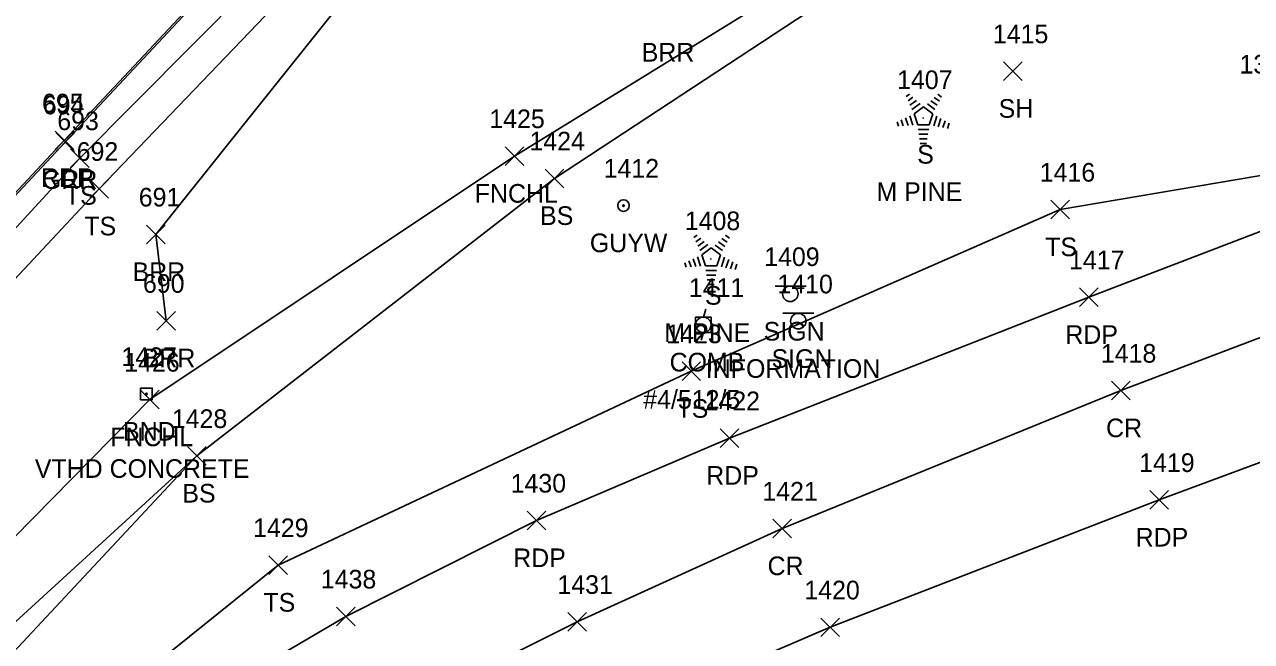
# Model space of a CAD drawing. Extents: x 1688195 to 1692013, y 424605 to 441234.
# Drawn here: x 1691586.4 to 1691718.1, y 439041.4 to 439107.6 of the extents above; entities that cross this region are included whole.
import ezdxf

# ---------------------------------------------------------------- set-up
doc = ezdxf.new("R2010")
doc.units = 0
for name, color, linetype in [('L_A', 7, 'Continuous'), ('L_C', 7, 'Continuous'), ('L_I', 7, 'Continuous'), ('L_TIC', 7, 'Continuous'), ('LABL', 7, 'Continuous'), ('LELB', 7, 'Continuous'), ('Level 18', 7, 'Continuous'), ('LFNC', 7, 'Continuous'), ('LTC', 7, 'Continuous'), ('M_A', 7, 'Continuous'), ('M_C', 7, 'Continuous'), ('M_I', 7, 'Continuous'), ('P_A', 7, 'Continuous'), ('P_I', 7, 'Continuous'), ('P_TIC', 7, 'Continuous'), ('PET', 7, 'Continuous'), ('PRC', 7, 'Continuous'), ('R_A', 7, 'Continuous'), ('R_I', 7, 'Continuous'), ('R_TIC', 7, 'Continuous'), ('RGR', 7, 'Continuous'), ('S_A', 7, 'Continuous'), ('S_C', 7, 'Continuous'), ('S_I', 7, 'Continuous'), ('SSGN', 7, 'Continuous'), ('U_A', 7, 'Continuous'), ('U_C', 7, 'Continuous'), ('U_I', 7, 'Continuous'), ('UP', 7, 'Continuous'), ('UPGW', 7, 'Continuous')]:
    doc.layers.add(name, color=color, linetype=linetype)

msp = doc.modelspace()

# ---------------------------------------------------------------- linework, layer by layer
at = {"layer": 'L_TIC'}
for points in [[(1691691.44, 439101.58), (1691693.44, 439103.58)], [(1691693.44, 439101.58), (1691691.44, 439103.58)], [(1691591.32, 439092.25), (1691593.32, 439094.25)], [(1691593.32, 439092.25), (1691591.32, 439094.25)], [(1691637.96, 439092.47), (1691639.96, 439094.47)], [(1691639.96, 439092.47), (1691637.96, 439094.47)], [(1691642.28, 439090.08), (1691644.28, 439092.08)], [(1691644.28, 439090.08), (1691642.28, 439092.08)], [(1691593.4, 439088.96), (1691595.4, 439090.96)], [(1691595.4, 439088.96), (1691593.4, 439090.96)], [(1691696.52, 439086.73), (1691698.52, 439088.73)], [(1691698.52, 439086.73), (1691696.52, 439088.73)], [(1691599.49, 439084.06), (1691601.49, 439086.06)], [(1691601.49, 439084.06), (1691599.49, 439086.06)], [(1691600.59, 439074.8), (1691602.59, 439076.8)], [(1691602.59, 439074.8), (1691600.59, 439076.8)], [(1691656.95, 439069.39), (1691658.95, 439071.39)], [(1691658.95, 439069.39), (1691656.95, 439071.39)], [(1691598.84, 439066.34), (1691600.84, 439068.34)], [(1691600.84, 439066.34), (1691598.84, 439068.34)], [(1691603.89, 439060.29), (1691605.89, 439062.29)], [(1691605.89, 439060.29), (1691603.89, 439062.29)], [(1691603.89, 439060.29), (1691605.89, 439062.29)], [(1691605.89, 439060.29), (1691603.89, 439062.29)], [(1691612.62, 439048.58), (1691614.62, 439050.58)], [(1691614.62, 439048.58), (1691612.62, 439050.58)]]:
    msp.add_lwpolyline(points, dxfattribs=at)
at = {"layer": 'LABL'}
msp.add_lwpolyline([(1691601.59, 439075.8), (1691600.49, 439085.06), (1691627.74, 439119.17), (1691640.71, 439127.56), (1691655.14, 439108.61), (1691685.11, 439134.92), (1691687.62, 439141.73), (1691698.9, 439155.76), (1691733.43, 439157.4), (1691776.41, 439186.57), (1691794.38, 439190.21)], dxfattribs=at)
at = {"layer": 'LELB'}
for points in [[(1691809.05, 439198.7), (1691810.07, 439220.42), (1691810.47, 439227.71), (1691810.04, 439233.75), (1691820.98, 439231.16), (1691837.25, 439226.41), (1691844.55, 439222.68), (1691860.67, 439213.28), (1691879.41, 439197.19), (1691884.86, 439187.77), (1691888.44, 439178.13), (1691882, 439154.55), (1691849.25, 439142.61), (1691815.33, 439128.47), (1691761.5, 439106.68), (1691722.87, 439092.03), (1691697.52, 439087.73), (1691657.95, 439070.39), (1691613.62, 439049.58), (1691576.98, 439020.14), (1691544.83, 438993.15), (1691508.2, 438954.88), (1691488.69, 438935.2)], [(1691494.97, 438989.23), (1691529.39, 439026.47), (1691563.11, 439061.46), (1691592.32, 439093.25), (1691622.45, 439123.57), (1691640.28, 439144.55), (1691642.63, 439146.18), (1691644.54, 439148.64), (1691657.14, 439160.25), (1691677.5, 439185.53), (1691687.79, 439198.06), (1691700.53, 439206.6), (1691711.71, 439214.4), (1691729.93, 439221), (1691765.22, 439228.65), (1691785.8, 439230.06)], [(1691867.08, 439165.21), (1691844.95, 439160.27), (1691798.84, 439152.11), (1691745.51, 439147.11), (1691728.71, 439142.4), (1691709.09, 439133.88), (1691683, 439117.2), (1691643.28, 439091.08), (1691604.89, 439061.29), (1691572.53, 439026.72), (1691542.38, 438995.55), (1691505.84, 438957.5), (1691487.66, 438936.34), (1691466.81, 438915.54), (1691436.02, 438880.86), (1691415.55, 438858.76)], [(1691497.62, 438986.55), (1691532.48, 439023.13), (1691565.52, 439059.1), (1691594.4, 439089.96), (1691624.94, 439121.84), (1691642.24, 439143.61)], [(1691604.89, 439061.29), (1691570.2, 439029.58), (1691540.68, 438997.55), (1691504.19, 438958.83), (1691485.94, 438937.8), (1691466.29, 438916.24), (1691434.59, 438882.45), (1691414.01, 438860.1)]]:
    msp.add_lwpolyline(points, dxfattribs=at)
at = {"layer": 'Level 18'}
msp.add_lwpolyline([(1691598.85, 439068.57), (1691600.1, 439068.57), (1691600.1, 439067.32), (1691598.85, 439067.32)], close=True, dxfattribs=at)
msp.add_circle((1691599.48, 439067.94), 0.0833, dxfattribs=at)
at = {"layer": 'LFNC'}
msp.add_lwpolyline([(1691844.63, 439219.19), (1691827.3, 439208.18), (1691808.98, 439197.07), (1691805.18, 439194.78), (1691802.65, 439193.15), (1691780.93, 439179.95), (1691740.49, 439155.55), (1691707.63, 439134.9), (1691682.09, 439120.04), (1691638.96, 439093.47), (1691599.84, 439067.34), (1691566.38, 439033.38), (1691536.95, 439001.22), (1691500.89, 438961.26), (1691462.91, 438919.55), (1691429.39, 438883.14), (1691411.26, 438863.12)], dxfattribs=at)
at = {"layer": 'LTC'}
for p, q in [((1691681, 439099.87), (1691681.35, 439100.12)), ((1691681.21, 439099.4), (1691681.73, 439099.79)), ((1691681.41, 439098.94), (1691682.12, 439099.45)), ((1691683.65, 439099.41), (1691684.33, 439098.92)), ((1691684.02, 439099.76), (1691684.57, 439099.36)), ((1691684.39, 439100.11), (1691684.81, 439099.8)), ((1691681.62, 439098.47), (1691682.5, 439099.11)), ((1691681.85, 439098.01), (1691682.86, 439098.75)), ((1691681.85, 439098.01), (1691682.24, 439096.82)), ((1691682.86, 439098.75), (1691683.86, 439098.02)), ((1691683.28, 439099.06), (1691684.09, 439098.47)), ((1691683.86, 439098.02), (1691683.47, 439096.82)), ((1691680.03, 439097.15), (1691680.18, 439096.68)), ((1691680.48, 439097.36), (1691680.7, 439096.71)), ((1691680.94, 439097.58), (1691681.21, 439096.74)), ((1691681.39, 439097.8), (1691681.73, 439096.78)), ((1691683.47, 439096.82), (1691682.24, 439096.82)), ((1691684.3, 439097.75), (1691683.96, 439096.71)), ((1691684.74, 439097.5), (1691684.45, 439096.62)), ((1691685.18, 439097.25), (1691684.95, 439096.52)), ((1691685.63, 439097), (1691685.44, 439096.43)), ((1691683.43, 439096.32), (1691682.28, 439096.32)), ((1691683.34, 439095.82), (1691682.36, 439095.82)), ((1691683.26, 439095.32), (1691682.43, 439095.32)), ((1691683.18, 439094.82), (1691682.5, 439094.82)), ((1691658.22, 439084.73), (1691658.57, 439084.99)), ((1691661.61, 439084.97), (1691662.03, 439084.66)), ((1691658.43, 439084.26), (1691658.96, 439084.65)), ((1691658.64, 439083.8), (1691659.34, 439084.31)), ((1691658.85, 439083.33), (1691659.72, 439083.97)), ((1691659.07, 439082.88), (1691660.08, 439083.61)), ((1691660.08, 439083.61), (1691661.08, 439082.89)), ((1691660.5, 439083.92), (1691661.31, 439083.33)), ((1691660.87, 439084.27), (1691661.55, 439083.78)), ((1691661.24, 439084.62), (1691661.79, 439084.22)), ((1691657.7, 439082.22), (1691657.92, 439081.57)), ((1691658.16, 439082.44), (1691658.43, 439081.61)), ((1691658.62, 439082.66), (1691658.95, 439081.64)), ((1691659.07, 439082.88), (1691659.46, 439081.68)), ((1691661.08, 439082.89), (1691660.69, 439081.68)), ((1691661.52, 439082.61), (1691661.18, 439081.58)), ((1691661.96, 439082.36), (1691661.67, 439081.48)), ((1691662.41, 439082.11), (1691662.17, 439081.38)), ((1691657.25, 439082.01), (1691657.4, 439081.54)), ((1691660.69, 439081.68), (1691659.46, 439081.68)), ((1691660.65, 439081.18), (1691659.5, 439081.18)), ((1691662.85, 439081.86), (1691662.66, 439081.29)), ((1691660.57, 439080.68), (1691659.58, 439080.68)), ((1691660.48, 439080.18), (1691659.65, 439080.18)), ((1691660.4, 439079.68), (1691659.72, 439079.68))]:
    msp.add_line(p, q, dxfattribs=at)
at = {"layer": 'P_TIC'}
for points in [[(1691589.68, 439094.16), (1691591.68, 439096.16)], [(1691591.68, 439094.16), (1691589.68, 439096.16)], [(1691699.6, 439077.32), (1691701.6, 439079.32)], [(1691701.6, 439077.32), (1691699.6, 439079.32)], [(1691703.03, 439067.3), (1691705.03, 439069.3)], [(1691705.03, 439067.3), (1691703.03, 439069.3)], [(1691661.06, 439062.2), (1691663.06, 439064.2)], [(1691663.06, 439062.2), (1691661.06, 439064.2)], [(1691707.14, 439055.57), (1691709.14, 439057.57)], [(1691709.14, 439055.57), (1691707.14, 439057.57)], [(1691640.34, 439053.36), (1691642.34, 439055.36)], [(1691642.34, 439053.36), (1691640.34, 439055.36)], [(1691666.7, 439052.5), (1691668.7, 439054.5)], [(1691668.7, 439052.5), (1691666.7, 439054.5)], [(1691619.88, 439043.07), (1691621.88, 439045.07)], [(1691621.88, 439043.07), (1691619.88, 439045.07)], [(1691644.71, 439042.49), (1691646.71, 439044.49)], [(1691646.71, 439042.49), (1691644.71, 439044.49)], [(1691671.86, 439041.9), (1691673.86, 439043.9)], [(1691673.86, 439041.9), (1691671.86, 439043.9)]]:
    msp.add_lwpolyline(points, dxfattribs=at)
at = {"layer": 'PET'}
for points in [[(1691527.98, 439028.02), (1691561.01, 439063.43), (1691590.68, 439095.16), (1691619.98, 439126.48), (1691638.57, 439146.32), (1691653.83, 439162.94), (1691673.33, 439185.49), (1691673.65, 439189.01), (1691685.04, 439200.74), (1691697.53, 439210.68), (1691709.71, 439218.34), (1691715.71, 439221.67), (1691737.08, 439230.06)], [(1691962.88, 439130.56), (1691955.64, 439134.26), (1691948.02, 439136.72), (1691941.11, 439138.03), (1691934.22, 439138.24), (1691927.22, 439137.24), (1691921.33, 439135.77), (1691915.1, 439134.27), (1691873.49, 439117.66), (1691865.77, 439114.89), (1691827.16, 439101.41), (1691792.77, 439088.6), (1691761.14, 439076.62), (1691734.19, 439066.23), (1691708.14, 439056.57), (1691672.86, 439042.9), (1691649.54, 439032.89)], [(1691724.96, 439087.65), (1691700.6, 439078.32), (1691662.06, 439063.2), (1691641.34, 439054.36), (1691620.88, 439044.07), (1691602.22, 439033.1)]]:
    msp.add_lwpolyline(points, dxfattribs=at)
at = {"layer": 'PRC'}
msp.add_lwpolyline([(1691888.13, 439193.66), (1691921.53, 439164.99), (1691933.61, 439155.1), (1691905.33, 439143.8), (1691864.7, 439127.18), (1691822.78, 439112.3), (1691787.26, 439099.58), (1691756.92, 439088.3), (1691729.19, 439077.85), (1691704.03, 439068.3), (1691667.7, 439053.5), (1691645.71, 439043.49), (1691628.46, 439034.88), (1691608.73, 439022.92), (1691585.22, 439006.39), (1691574.92, 438998.75), (1691559.84, 438985.93), (1691543.5, 438970.76), (1691518.61, 438946.02), (1691478.27, 438903.21), (1691447.81, 438870), (1691426.94, 438847.45)], dxfattribs=at)
at = {"layer": 'R_TIC'}
for points in [[(1691589.77, 439093.95), (1691591.77, 439095.95)], [(1691591.77, 439093.95), (1691589.77, 439095.95)]]:
    msp.add_lwpolyline(points, dxfattribs=at)
at = {"layer": 'RGR'}
msp.add_lwpolyline([(1691392.43, 438882.91), (1691415.63, 438907.66), (1691443.42, 438937.01), (1691473.56, 438969.15), (1691494.4, 438991.79), (1691528.19, 439027.86), (1691561.17, 439063.3), (1691590.77, 439094.95), (1691620.16, 439126.42), (1691638.64, 439146.14), (1691654.09, 439162.7)], dxfattribs=at)
at = {"layer": 'SSGN'}
for p, q in [((1691666.93, 439079.52), (1691670.26, 439079.52)), ((1691668.57, 439078.69), (1691668.57, 439078.69)), ((1691667.78, 439076.6), (1691671.11, 439076.6)), ((1691669.43, 439075.76), (1691669.43, 439075.76))]:
    msp.add_line(p, q, dxfattribs=at)
for centre in [(1691668.57, 439078.69), (1691669.43, 439075.76)]:
    msp.add_circle(centre, 0.833, dxfattribs=at)
at = {"layer": 'UP'}
for p, q in [((1691659.49, 439077.03), (1691659.24, 439076.2)), ((1691658.4, 439074.53), (1691658.4, 439076.2)), ((1691658.4, 439076.2), (1691660.07, 439076.2)), ((1691660.07, 439076.2), (1691660.07, 439074.53)), ((1691660.07, 439074.53), (1691658.4, 439074.53)), ((1691658.99, 439073.7), (1691659.24, 439074.53)), ((1691659.24, 439075.36), (1691659.24, 439075.36))]:
    msp.add_line(p, q, dxfattribs=at)
msp.add_circle((1691659.24, 439075.36), 0.833, dxfattribs=at)
at = {"layer": 'UPGW'}
for radius in [0.625, 0.0833]:
    msp.add_circle((1691650.67, 439088.16), radius, dxfattribs=at)

# ---------------------------------------------------------------- texts
at = {"layer": 'L_A'}
for s, p in [('BRR', (1691652.63, 439103.61)), ('SH', (1691690.93, 439097.58)), ('S', (1691682.19, 439092.66)), ('TS', (1691590.73, 439088.25)), ('FNCHL', (1691634.71, 439088.47)), ('BS', (1691641.72, 439086.08)), ('TS', (1691592.81, 439084.96)), ('TS', (1691695.93, 439082.73)), ('BRR', (1691597.98, 439080.06)), ('S', (1691659.41, 439077.52)), ('BRR', (1691599.08, 439070.8)), ('TS', (1691656.36, 439065.39)), ('FNCHL', (1691595.59, 439062.34)), ('BS', (1691603.33, 439056.29)), ('BS', (1691603.33, 439056.29)), ('TS', (1691612.03, 439044.58))]:
    msp.add_text(s, height=2, dxfattribs=at).set_placement(p)
at = {"layer": 'L_C'}
for p in [(1691677.82, 439088.66), (1691655.05, 439073.52)]:
    msp.add_text('M PINE', height=2, dxfattribs=at).set_placement(p)
at = {"layer": 'L_I'}
for s, p in [('1415', (1691690.31, 439105.58)), ('1362', (1691716.78, 439102.33)), ('1407', (1691680.03, 439100.66)), ('693', (1691589.91, 439096.25)), ('1425', (1691636.27, 439096.47)), ('1424', (1691640.58, 439094.08)), ('692', (1691591.99, 439092.96)), ('1416', (1691695.34, 439090.73)), ('691', (1691598.65, 439088.06)), ('1408', (1691657.25, 439085.52)), ('690', (1691599.1, 439078.8)), ('1423', (1691655.26, 439073.39)), ('1426', (1691597.09, 439070.34)), ('1428', (1691602.2, 439064.29)), ('1428', (1691602.2, 439064.29)), ('1429', (1691610.92, 439052.58))]:
    msp.add_text(s, height=2, dxfattribs=at).set_placement(p)
at = {"layer": 'LTC'}
for p in [(1691682.74, 439097.76), (1691659.96, 439082.62)]:
    msp.add_text('.', height=1.04, rotation=270, dxfattribs=at).set_placement(p)
at = {"layer": 'M_A'}
msp.add_text('BND', height=2, dxfattribs=at).set_placement((1691596.97, 439062.94))
at = {"layer": 'M_C'}
msp.add_text('VTHD CONCRETE', height=2, dxfattribs=at).set_placement((1691587.5, 439058.94))
at = {"layer": 'M_I'}
msp.add_text('1427', height=2, dxfattribs=at).set_placement((1691596.79, 439070.94))
at = {"layer": 'P_A'}
for s, p in [('RDP', (1691588.17, 439090.16)), ('RDP', (1691698.09, 439073.32)), ('CR', (1691702.46, 439063.3)), ('RDP', (1691659.55, 439058.2)), ('RDP', (1691705.63, 439051.57)), ('RDP', (1691638.83, 439049.36)), ('CR', (1691666.13, 439048.5))]:
    msp.add_text(s, height=2, dxfattribs=at).set_placement(p)
at = {"layer": 'P_I'}
for s, p in [('695', (1691588.27, 439098.16)), ('1417', (1691698.48, 439081.32)), ('1418', (1691701.9, 439071.3)), ('1422', (1691659.37, 439066.2)), ('1419', (1691706.01, 439059.57)), ('1430', (1691638.56, 439057.36)), ('1421', (1691665.57, 439056.5)), ('1438', (1691618.19, 439047.07)), ('1431', (1691643.58, 439046.49)), ('1420', (1691670.08, 439045.9))]:
    msp.add_text(s, height=2, dxfattribs=at).set_placement(p)
at = {"layer": 'R_A'}
msp.add_text('GRR', height=2, dxfattribs=at).set_placement((1691588.26, 439089.95))
at = {"layer": 'R_I'}
msp.add_text('694', height=2, dxfattribs=at).set_placement((1691588.36, 439097.95))
at = {"layer": 'S_A'}
for p in [(1691665.71, 439073.67), (1691666.56, 439070.74)]:
    msp.add_text('SIGN', height=2, dxfattribs=at).set_placement(p)
at = {"layer": 'S_C'}
msp.add_text('INFORMATION', height=2, dxfattribs=at).set_placement((1691659.51, 439069.67))
at = {"layer": 'S_I'}
for s, p in [('1409', (1691665.77, 439081.67)), ('1410', (1691667.19, 439078.74))]:
    msp.add_text(s, height=2, dxfattribs=at).set_placement(p)
at = {"layer": 'U_A'}
for s, p in [('GUYW', (1691647.06, 439083.16)), ('COMB', (1691655.62, 439070.36))]:
    msp.add_text(s, height=2, dxfattribs=at).set_placement(p)
at = {"layer": 'U_C'}
msp.add_text('#4/512/5', height=2, dxfattribs=at).set_placement((1691652.79, 439066.36))
at = {"layer": 'U_I'}
for s, p in [('1412', (1691648.54, 439091.16)), ('1411', (1691657.68, 439078.36))]:
    msp.add_text(s, height=2, dxfattribs=at).set_placement(p)

doc.saveas('drawing.dxf')
